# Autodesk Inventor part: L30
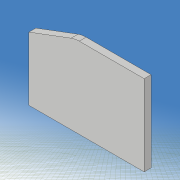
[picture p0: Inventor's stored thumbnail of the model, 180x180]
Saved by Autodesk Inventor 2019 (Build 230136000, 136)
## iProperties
Created: 2021-05
Part Number: L30
Material: 一般
Document SubType Name: Modeling
Designer: kikut
Density: 1 g/cm^3
Appearance: 既定
Mass: 0.00934248 g
Surface Area: 0.426451 cm^2
Volume: 0.00934248 cm^3
Author: kikut
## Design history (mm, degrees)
sketch "スケッチ1"
  geometry: L1 (80, 60)-(-80, 60); L2 (-80, 60)-(-80, -60); L3 (-80, -60)-(80, -60); L4 (80, -60)-(80, 60); L5 (80, 60)-(-80, -60); L6 (-80, 60)-(80, -60); 1 further point
  constraints: 12 end point, 2 midpoint, 2 parallel, 1 horizontal, 1 perpendicular
  dimensions: "d0" = 160 distance of L2.end L3.end; "d1" = 120 distance of L1.end L2.end
extrude "押し出し1" new body sketch "スケッチ1" stored distance "d2" = 0.6; taper "d3" = 0 deg
sketch "スケッチ2"
  geometry: L1 (-140, 0)-(140, 0) reference; L2 (0, -54)-(20, -30); L3 (0, 54)-(20, 30); L4 (0, -3)-(6.514, -3); L5 (6.514, -3)-(16, -6); L6 (16, -6)-(24, -3); L7 (24, -3)-(33.716, -3); L8 (0, 3)-(6.514, 3); L9 (6.514, 3)-(16, 6); L10 (16, 6)-(24, 3); L11 (24, 3)-(33.716, 3); L12 (0, -98)-(0, 98) reference; L13 (-100, -70)-(100, -70); L14 (100, -70)-(100, 70); L15 (100, 70)-(-100, 70); L16 (-100, 70)-(-100, -70); L17 (-100, -70)-(100, 70); L18 (100, -70)-(-100, 70); A1 r 60 centre (54.312, 28.5) between (0, 54) and (0, 3); A2 r 60 centre (54.312, -28.5) between (0, -3) and (0, -54); A3 r 18.111 centre (18, -12) between (20, -30) and (33.716, -3); A4 r 18.111 centre (18, 12) between (33.716, 3) and (20, 30); 1 further point
  constraints: 32 end point, 8 point on circle, 8 symmetric about line, 4 centre point, 3 horizontal, 2 collinear, 2 midpoint, 2 parallel, 1 perpendicular
  dimensions: "d5" = 60 radius of A1; "d6" = 6 distance of L8.start L4.start; "d7" = 108 distance of L3.start L2.start; "d8" = 0 horizontal distance of L3.start L8.start; "d9" = 60 distance of L3.end L2.end; "d10" = 0 horizontal distance of point (0, 0) L3.start; "d11" = 20 horizontal distance of L3.start L3.end; "d12" = 24 distance of A4.centre A3.centre; "d13" = 6 distance of L11.end L7.end; "d14" = 12 distance of L9.end L5.end; "d15" = 16 distance from line of L12 L5.end; "d16" = 24 distance from line of L6.end L12; "d17" = 200 distance of L14.end L15.end; "d18" = 140 distance of L15.end L13.start; "d30" = 18 distance from line of L12 A4.centre
extrude "押し出し2" cut sketch "スケッチ2" stored distance "d19" = 10; taper "d20" = 0 deg
sketch "スケッチ3"
  geometry: L1 (49.705, -17.97)-(33.948, -15.191); L2 (33.948, -15.191)-(34.295, -13.222); L3 (34.295, -13.222)-(50.052, -16); L4 (50.052, -16)-(49.705, -17.97); L5 (49.705, -17.97)-(34.295, -13.222); L6 (33.948, -15.191)-(50.052, -16); L7 (50.052, 16)-(34.295, 13.222); L8 (34.295, 13.222)-(33.948, 15.191); L9 (33.948, 15.191)-(49.705, 17.97); L10 (49.705, 17.97)-(50.052, 16); L11 (50.052, 16)-(33.948, 15.191); L12 (34.295, 13.222)-(49.705, 17.97); L13 (-112, 0)-(112, 0) reference; L14 (0, -84)-(0, 84) reference; 3 further points
  constraints: 24 end point, 4 midpoint, 4 parallel, 2 perpendicular, 2 symmetric about line
  dimensions: "d21" = 2 distance of L3.end L1.start; "d22" = 2 distance of L9.end L7.start; "d23" = 16 distance of L8.end L9.end; "d24" = 42 distance from line of L14 point (42, 15.596); "d26" = 10 deg angle of L7 L13; "d62" = 16 distance from line of L3.end L13
extrude "押し出し3" join sketch "スケッチ3" distance "d27" = 0.6; taper "d28" = 0 deg
fillet "フィレット1" dims "d31" = 2
fillet "フィレット2" dims "d32" = 1
sketch "スケッチ7"
  geometry: L1 (-20, 60)-(80, 60); L2 (80, 60)-(80, -60); L3 (80, -60)-(-20, -60); L4 (-20, -60)-(-20, 60); L5 (0, -82.207)-(0, 85.793) reference; L6 (-40, 0)-(100, 0) reference; L7 (20, 0)-(30, 0); L8 (30, 0)-(30, -10); L9 (30, -10)-(20, -10); L10 (20, -10)-(20, 0); 1 further point
  constraints: 16 end point, 4 parallel, 2 horizontal, 2 perpendicular, 1 other
  dimensions: "d80" = 120 distance of L3.end L1.start; "d81" = 20 distance between parallel lines of L5 L4; "d82" = 100 distance of L1.start L1.end; "d84" = 10 distance of L8.end L9.end; "d85" = 10 distance of L7.end L8.end; "d86" = 40 distance between parallel lines of L4 L10; "d92" = 0 distance between parallel lines of L7 L6
extrude "押し出し5" cut sketch "スケッチ7" stored distance "d87" = 10; taper "d88" = 0 deg
node "ソリッド1"
